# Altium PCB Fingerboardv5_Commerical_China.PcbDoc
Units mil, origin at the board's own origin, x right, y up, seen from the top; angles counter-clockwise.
Board outline 600 x 1050 mil, 2 copper layers (Top Layer, Bottom Layer); 12 components, 14 nets, 70 pads, 13 vias.
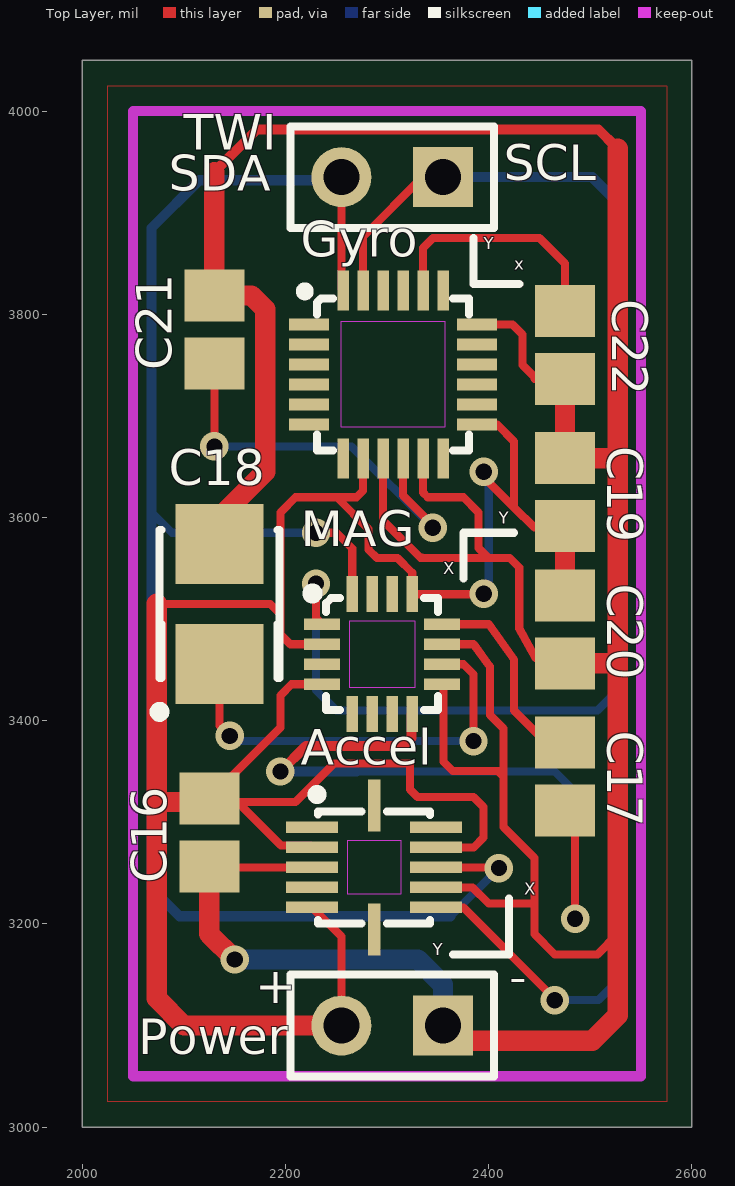
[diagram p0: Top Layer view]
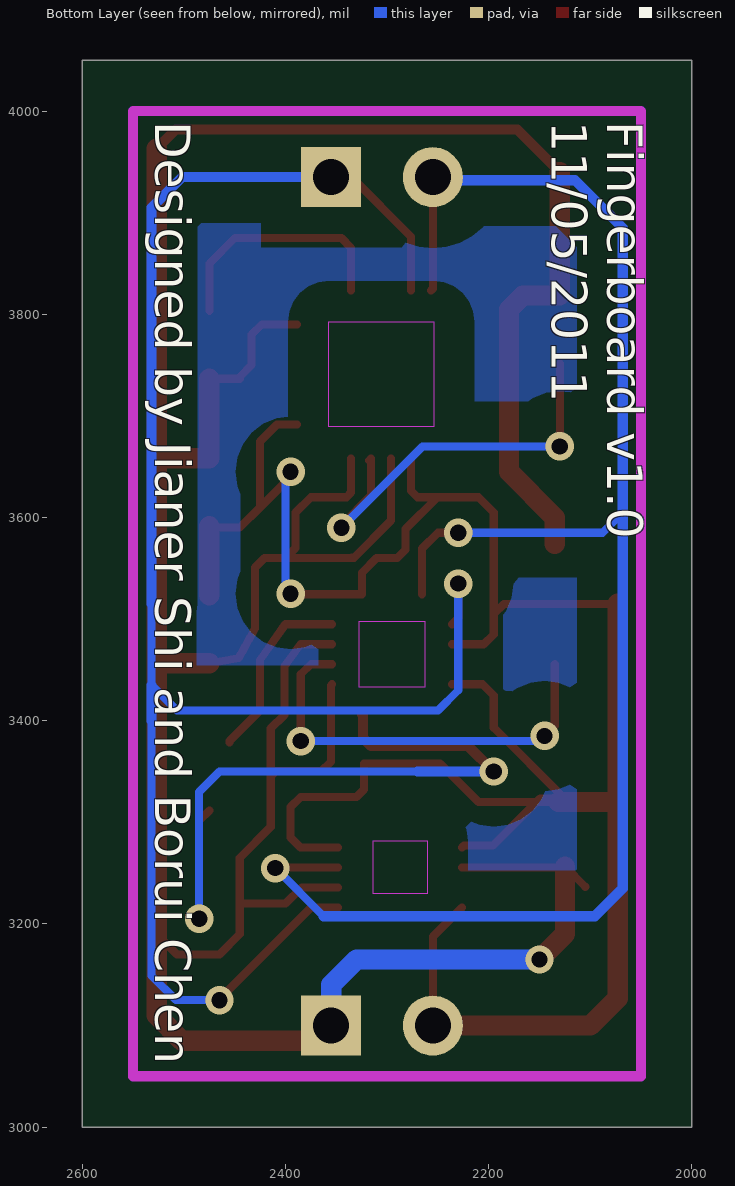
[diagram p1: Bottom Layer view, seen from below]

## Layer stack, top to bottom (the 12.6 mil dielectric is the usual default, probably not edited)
Top Layer: signal copper 1.4
Dielectric: dielectric 12.6, FR-4, Dk 4.8
Bottom Layer: signal copper 1.4

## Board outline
2000,3000 2600,3000 2600,4050 2000,4050

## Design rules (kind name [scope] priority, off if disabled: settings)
Clearance "Polygon Clearance" [InPolygon] p1: gap=40
Clearance [All] p2: gap=8.1
HoleSize [All] p1: absolutevalues=TRUE maxlimit=100 minlimit=16 maxpercent=80.000 minpercent=20.000
MinimumAnnularRing [All] p1: minimumring=6
PolygonConnect [All] p1: connectstyle=Relief reliefconductorwidth=10 reliefentries=4 polygonreliefangle="90 Angle"
RoutingVias [All] p1: holewidth=16 width=28 viastyle="Through Hole" minholewidth=16 minwidth=27 maxholewidth=16 maxwidth=35
SilkscreenOverComponentPads [All] p1: minsilkscreentomaskgap=10
SolderMaskExpansion [All] p1: expansion=4
Width [All] p1: maxlimit=50 minlimit=8 preferedwidth=8
26 further rules are at their usual default settings.

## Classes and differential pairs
component class Fingerboard: Power TWI
component class U_BMA180: Accel C16
component class U_HMC5883L: C17 C18 MAG
component class U_IMU3000: C19 C20 C21 C22 Gyro
net class AUX_TWI[1..0]: AUX_TWI0 AUX_TWI1
net class TWI[1..0]: TWI0 TWI1

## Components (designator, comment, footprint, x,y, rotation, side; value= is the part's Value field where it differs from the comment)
Accel "BMA180" "BMA180 - ECESHOP" 2240,3295 r270 top
C16 "Cap Semi" CAPC2012N 2125,3290 r90 top
C17 "Cap Semi" CAPC2012N 2475,3345 r90 top
C18 "Cap Pol1" TC3528-1411 2135,3515 r90 top
C19 "Cap Semi" CAPC2012N 2475,3625 r270 top
C20 "Cap Semi" CAPC2012N 2475,3490 r90 top
C21 "Cap Semi" CAPC2012N 2130,3785 r270 top
C22 "Cap Semi" CAPC2012N 2475,3770 r90 top
Gyro "IMU3000" "IMU3000 - ECESHOP" 2235,3790 r0 top
MAG "HMC5883L" "HMC5883L - ECESHOP" 2245,3495 r0 top
Power "Header 2" HDR1X2 2355,3100 r180 top
TWI "TWI" HDR1X2 2355,3935 r180 top

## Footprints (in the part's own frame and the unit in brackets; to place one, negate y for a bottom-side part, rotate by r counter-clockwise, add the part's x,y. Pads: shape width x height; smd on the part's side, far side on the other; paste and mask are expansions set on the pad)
"BMA180 - ECESHOP" [mm] "BMA180 - ECESHOP"
  rect 0.29x1.3 smd: 1(0,-0.35) 2(0.5,-0.35) 3(1,-0.35) 4(1.5,-0.35) 5(2,-0.35) 7(2,2.75) 8(1.5,2.75) 9(1,2.75) 10(0.5,2.75) 11(0,2.75)
  rect 1.3x0.32 smd: 6(2.55,1.2) 12(-0.55,1.2)
  Keep-Out Layer region: 0.328,0.524 1.658,0.524 1.658,1.876 0.328,1.876
  silkscreen extent -0.91,-0.31 2.4,2.6
CAPC2012N [mm] "Chip Capacitor, Body 2.0x1.3mm, IPC Medium Density"
  rect 1.3x1.5 smd: 1(-0.85,0) 2(0.85,0)
  body extent -1.1,-0.72 1.1,0.72, height 1.1
HDR1X2 [mm] "Connector; Header; 2 Position"
  rect 1.5x1.5 hole 0.9: 1(0,0)
  round 1.5 hole 0.9: 2(2.54,0)
  silkscreen extent -1.27,-1.27 3.81,1.27
"HMC5883L - ECESHOP" [mm]
  rect 0.9x0.29 smd: 1(-0.225,0) 2(-0.225,-0.5) 3(-0.225,-1) 4(-0.225,-1.5) 9(2.775,-1.5) 10(2.775,-1) 11(2.775,-0.5) 12(2.775,0)
  rect 0.29x0.9 smd: 5(0.525,-2.25) 6(1.025,-2.25) 7(1.525,-2.25) 8(2.025,-2.25) 13(2.025,0.75) 14(1.525,0.75) 15(1.025,0.75) 16(0.525,0.75)
  Keep-Out Layer region: 0.452,-1.572 2.099,-1.572 2.099,0.075 0.452,0.075
  silkscreen extent -0.57,-2.15 2.67,0.87
"IMU3000 - ECESHOP" [mm]
  rect 1x0.29 smd: 1(-0.3,0) 2(-0.3,-0.5) 3(-0.3,-1) 4(-0.3,-1.5) 5(-0.3,-2) 6(-0.3,-2.5) 13(3.9,-2.5) 14(3.9,-2) 15(3.9,-1.5) 16(3.9,-1) 17(3.9,-0.5) 18(3.9,0)
  rect 0.29x1 smd: 7(0.55,-3.35) 8(1.05,-3.35) 9(1.55,-3.35) 10(2.05,-3.35) 11(2.55,-3.35) 12(3.05,-3.35) 19(3.05,0.85) 20(2.55,0.85) 21(2.05,0.85) 22(1.55,0.85) 23(1.05,0.85) 24(0.55,0.85)
  Keep-Out Layer region: 0.488,-2.562 3.109,-2.562 3.109,0.066 0.488,0.066
  silkscreen extent -0.48,-3.15 3.7,0.9
TC3528-1411 [mm] "Capacitor, SM Tantalum; Body 3.5 x 2.8 mm (LxW typ)"
  rect 2x2.2 smd: 1(-1.5,0) 2(1.5,0)
  silkscreen extent -2.82,-1.5 1.85,1.62

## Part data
C16 C17 C19 C20 C21 C22: "Capacitor (Semiconductor SIM Model)"
C18: "Polarized Capacitor (Radial)"
Power: "Header, 2-Pin"
TWI: library part "Header 2", "Header, 2-Pin"

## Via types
v1: diameter 28, hole 16, Top Layer to Bottom Layer, 13 vias

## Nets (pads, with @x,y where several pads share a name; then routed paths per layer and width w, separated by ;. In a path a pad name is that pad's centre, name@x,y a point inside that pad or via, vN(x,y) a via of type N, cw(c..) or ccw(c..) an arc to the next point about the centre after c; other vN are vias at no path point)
3.3VCC: Accel.2 Accel.5 Accel.10 C16.2 C19.2 C20.2 Gyro.8 Gyro.13 MAG.2 MAG.4 MAG.13 Power.2 | length 2496.6
  Top Layer w8: 2073.1,3515 2185,3515 2195,3505 ; C16.2 C16.2@2125.33,3323.46 ; C16.2@2131.54,3320 C16.2@2152.81,3320 ; 2195,3320 2210,3320 2247.9,3357.9 2322.66,3357.9 2322.66,3332.34 2330,3325 2385,3325 2395,3315 2395,3285 2385.32,3275.32 Accel.10 ; 2205,3320 C16.2@2152.81,3320 ; Accel.5 2255,3187.48 Power.2 ; Accel.2 2224.34,3277.19 2195.62,3277.19 C16.2@2152.81,3320 ; MAG.4 2205.95,3435.95 2195,3425 2195,3393.14 C16.2@2125.33,3323.46 ; MAG.2 2205.32,3475.32 2205,3475 2195,3485 2195,3505 ; Gyro.8 2276.34,3626.34 2270,3620 2250.37,3620 ; Gyro.13 2408.43,3691.57 2425,3675 2425,3610 ; v1(2395,3525) 2394.53,3524.53 MAG.13 2324.72,3545.65 2310.37,3560 2290,3560 2281.77,3568.23 2281.77,3588.6 2250.37,3620 ; v1(2395,3645) 2395,3640 2425,3610 ; C19.2 2473.46,3590 2445,3590 2425,3610 ; C16.2@2125.33,3323.46 2149.34,3323.46 C16.2@2152.81,3320 ; 2195,3505 2195,3605 2210,3620 2250.37,3620
  Top Layer w20: 2073.1,3515 2073.1,3320 ; C16.2@2131.54,3320 2073.1,3320 ; Power.2 2100,3100 2073.1,3126.9 2073.1,3320 ; C20.2 C19.2
  Bottom Layer w8: v1(2395,3525) 2400,3530 2400,3640 v1(2395,3645)
AUX_TWI0: Gyro.7
AUX_TWI1: Gyro.6
GND: Accel.3 Accel.8 C16.1 C18.2 C19.1 C20.1 C21.1 C22.1 Gyro.9 Gyro.11 Gyro.18 MAG.9 MAG.11 Power.1 | length 3858.4
  Top Layer w8: C16.1@2105,3236.54 C16.1 2125.91,3255.63 Accel.3 ; Gyro.9 2296.02,3597.12 2332.74,3560.4 2334.6,3560.4 2335,3560 2400,3560 ; Gyro.11 2335.39,3624.61 2340,3620 2375,3620 2390,3605 2390,3570 2400,3560 ; Accel.8 2384.05,3235.95 2400,3220 2445,3220 ; MAG.9 2355.4,3434.8 2355.4,3359.6 2364.6,3350.4 2409.2,3350.4 2414.6,3345 ; MAG.11 2385,3475.32 2401.1,3453.36 2401.1,3405.76 2414.6,3392.26 2414.6,3345 ; Gyro.18 2423.37,3790 2433.37,3780 2433.37,3750 2445,3738.37 2445,3736.63 2474.91,3736.63 C22.1 ; C20.1@2470.59,3460.95 C20.1 2446.1,3461.75 2430,3490.81 2430,3550.69 2420.69,3560 2400,3560 ; 2526.9,3190 2506.9,3170 2465,3170 2445,3190 2445,3220 ; 2414.6,3345 2414.6,3295.4 2445,3265 2445,3220
  Top Layer w10: 2130,3940 2171.9,3981.9 2508.1,3981.9 2525,3965
  Top Layer w20: C16.1 2125,3190 v1(2150,3165) ; 2130,3940 C21.1 2166.54,3818.46 2180,3805 2180,3645 2135,3600 C18.2 ; Power.1 2370,3085 2501.9,3085 2526.9,3110 2526.9,3190 2526.9,3460 ; C20.1 2523.44,3456.54 2526.9,3460 ; C22.1 C19.1 2523.44,3658.46 2526.9,3655 ; 2526.9,3963.1 2526.9,3655 ; 2526.9,3460 2526.9,3655
  Bottom Layer w20: v1(2150,3165) 2330,3165 2355,3140 Power.1
NetAccel_4: Accel.4
NetC17_1: C17.1 MAG.8 | length 700.1
  Top Layer w8: C17.1 2485,3301.54 v1(2485,3205)
  Top Layer w10: v1(2195,3350) 2220,3375 2315.57,3375 2323.85,3383.27 2323.85,3405.54 MAG.8
  Bottom Layer w8: 2270,3350 2465,3350 2485,3330 v1(2485,3205)
  Bottom Layer w10: v1(2195,3350) 2270,3350
NetC17_2: C17.2 MAG.12 | length 182.7
  Top Layer w8: MAG.12 2400,3495 2425,3460 2425,3410 2455,3380 C17.2@2455,3378.46
NetC18_1: C18.1 MAG.10 | length 417.7
  Top Layer w8: C18.1 2135,3395 v1(2145,3385) ; MAG.10 2375.1,3455.63 2385,3445.73 v1(2385,3380)
  Bottom Layer w8: v1(2145,3385) 2150,3380 v1(2385,3380)
NetC21_2: C21.2 Gyro.10 | length 412.6
  Top Layer w8: v1(2130,3670) C21.2 ; Gyro.10@2317.58,3656.23 Gyro.10 2315.71,3621.52 2345,3592.23 v1(2345,3590)
  Bottom Layer w8: v1(2130,3670) 2265,3670 v1(2345,3590)
NetC22_2: C22.2 Gyro.20 | length 242.4
  Top Layer w8: Gyro.20 2335.39,3865.39 2345,3875 2450,3875 2475,3850 C22.2
NetGyro_12: Gyro.12
NetINT_3: MAG.15
TWI0: Accel.7 Gyro.23 MAG.1 TWI.1 | length 1801.4
  Top Layer w8: v1(2230,3535) 2230,3501.14 MAG.1 ; Gyro.23 2276.34,3876.34 2335,3935 TWI.1 ; Accel.7 2375,3216.26 2465,3126.26 v1(2465,3125)
  Bottom Layer w8: v1(2230,3535) 2230,3430 2250,3410 2506.9,3410 2531.9,3435 2531.9,3515 ; v1(2465,3125) 2507.9,3125 2531.9,3149 2531.9,3400
  Bottom Layer w10: TWI.1 2501.9,3935 2531.9,3905 2531.9,3515 ; 2531.9,3400 2531.9,3435
TWI1: Accel.9 Gyro.24 MAG.16 TWI.2 | length 1669.9
  Top Layer w8: v1(2230,3585) 2250,3585 2265.67,3569.33 MAG.16 ; TWI.2 2255,3825.12 Gyro.24 ; Accel.9 2409.37,3255.63 v1(2410,3255) v1@2404.37,3260.63
  Bottom Layer w8: 2068.1,3605 2088.1,3585 v1(2230,3585) ; 2362.5,3207.5 v1(2410,3255)
  Bottom Layer w10: TWI.2 2251.9,3931.9 2115,3931.9 2068.1,3885 2068.1,3605 2068.1,3235 2095.6,3207.5 2362.5,3207.5
pads on no net: Accel.1 Accel.6 Accel.11 Accel.12 Gyro.1 Gyro.2 Gyro.3 Gyro.4 Gyro.5 Gyro.14 Gyro.15 Gyro.16 Gyro.17 Gyro.19 Gyro.21 Gyro.22 MAG.3 MAG.5 MAG.6 MAG.7 MAG.14

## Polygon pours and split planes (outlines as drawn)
GND on Top Layer "Top Layer-GND" (solid, pour order 2): 2025,4025 2575,4025 2575,3025 2025,3025
GND on Bottom Layer "Bottom Layer-GND" (solid, pour order 4): 2025,4025 2575,4025 2575,3025 2025,3025

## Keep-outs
Keep-Out Layer:
  lines w10: 2050,3050 2550,3050 2550,4000 2050,4000 2050,3050

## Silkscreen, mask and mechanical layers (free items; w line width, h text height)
Top Overlay:
  lines w8: 2365,3170 2420,3170 2420,3225 ; 2375,3540 2375,3585 2425,3585 ; 2385,3875 2385,3830 2430,3830
  text "SCL" at 2415,3920 h60
  text "SDA" at 2085,3910 h60
  text "Y" at 2395,3860 h20
  text "x" at 2425,3840 h20
  text "Y" at 2410,3590 h20
  text "X" at 2355,3540 h20
  text "X" at 2435,3225 h20
  text "Y" at 2345,3165 h20
  text "-" at 2420,3120 h60
  text "+" at 2170,3110 h60
Bottom Overlay:
  text "Fingerboard v1.0" at 2095,3990 h60 r90
  text "11/05/2011" at 2150,3990 h60 r90
  text "Designed by Jianer Shi and Borui Chen" at 2540,3990 h60 r90

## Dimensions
2050,3050 to 2550,3050 on Mechanical 1
2050,3050 to 2050,4000 on Mechanical 1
